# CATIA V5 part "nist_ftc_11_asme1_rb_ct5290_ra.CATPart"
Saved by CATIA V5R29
Part number: nist_ftc_11_asme1
Nomenclature: nist_ftc_11_asme1
Source: Unknown
Bounding box of the stored display mesh (mm): x -31.5 to 31.5, y -31.5 to 31.5, z -1.5 to 1.498
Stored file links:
  E:\users\dgn\TPS V5\Import-export annotations\Step\PMI representation 2015\NIST UC\FTC\R29\nist_ftc_11_asme1_rb- V5R29.CATPart
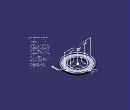
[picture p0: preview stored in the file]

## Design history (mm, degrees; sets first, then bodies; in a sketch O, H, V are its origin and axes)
TTRSSet1
f4a2d38f3ddc11d3a929006094b99c4b_11 "CATTPSSet"
AxisSystem1: origin (0, 0, -1.5), X (1, 0, 0), Y (0, 1, 0), Z (0, 0, 1)
Set1
  Point1: type Center, Curve edge [face of Solid1 | face of Solid1]
  Extract1: ExtractElem face of Solid1
  Extract2: ExtractElem face of Solid1
  Join1: Elements (Extract1; Extract2), ElementsToFederate (face of Solid1; face of Solid1)
Body1 "Solid1" (main body)
  Solid1: solid without history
